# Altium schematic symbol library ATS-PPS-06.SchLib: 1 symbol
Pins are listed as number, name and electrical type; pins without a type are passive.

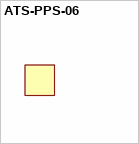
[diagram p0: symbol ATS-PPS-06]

## ATS-PPS-06
designator H?
PUSHPIN SPRING; Manufacturer: Advanced Thermal Solutions Inc; SymbolVersion: 2014 - 10 - 22; SymbolCreator: A0412036; CompType: Used in some BOM reports.  Useful for finding later.; U/M: each; Description: HEATSINK MUSIC WR SPRING 3.45MM
footprint ATS-PPS-06 (ATS PUSH PIN SPRING ATS-PPS-06)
